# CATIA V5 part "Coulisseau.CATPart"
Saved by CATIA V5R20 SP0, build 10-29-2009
Part number: Coulisseau
Bounding box of the stored display mesh (mm): x -25 to 75, y 17 to 60, z -20 to 23
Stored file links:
  D:\Dropbox\IAO_2011\MMS_GR1\abruchon\abruchon\Coulisseau.CATPart
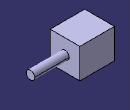
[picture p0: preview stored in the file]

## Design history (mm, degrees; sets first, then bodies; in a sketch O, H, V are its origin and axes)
Body1 (main body)
  Sketch1 on yz-plane, origin (0, 0, 0), H (0, 1, 0), V (0, 0, 1)
    line L1 (17, 23) -> (60, 23)
    line L2 (60, 23) -> (60, -20)
    line L3 (60, -20) -> (17, -20)
    line L4 (17, -20) -> (17, 23)
    length L2 = 43
    length L3 = 43
    horizontal: L1 H, L3 H
    vertical: L2 V, L4 V
  Pad1: profile Sketch1, direction (1, 0, 0), length 25, mirrored extent
  Sketch2 on end face of Pad1, origin (25, 0, 0), H (0, 1, 0), V (0, 0, 1)
    circle A1 centre (38.5, 1.5) radius 6
    point P1 (38.5, 1.5)
    reference projected line E1 (60, -20) -> (60, 23) from edge [face of Pad1 from Sketch1.L2 | end face of Pad1]
    reference projected line E2 (17, -20) -> (60, -20) from edge [face of Pad1 from Sketch1.L3 | end face of Pad1]
    distance P1 E1 = 21.5
    distance P1 E2 = 21.5
  Pad2: profile Sketch2, direction (1, 0, 0), length 50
